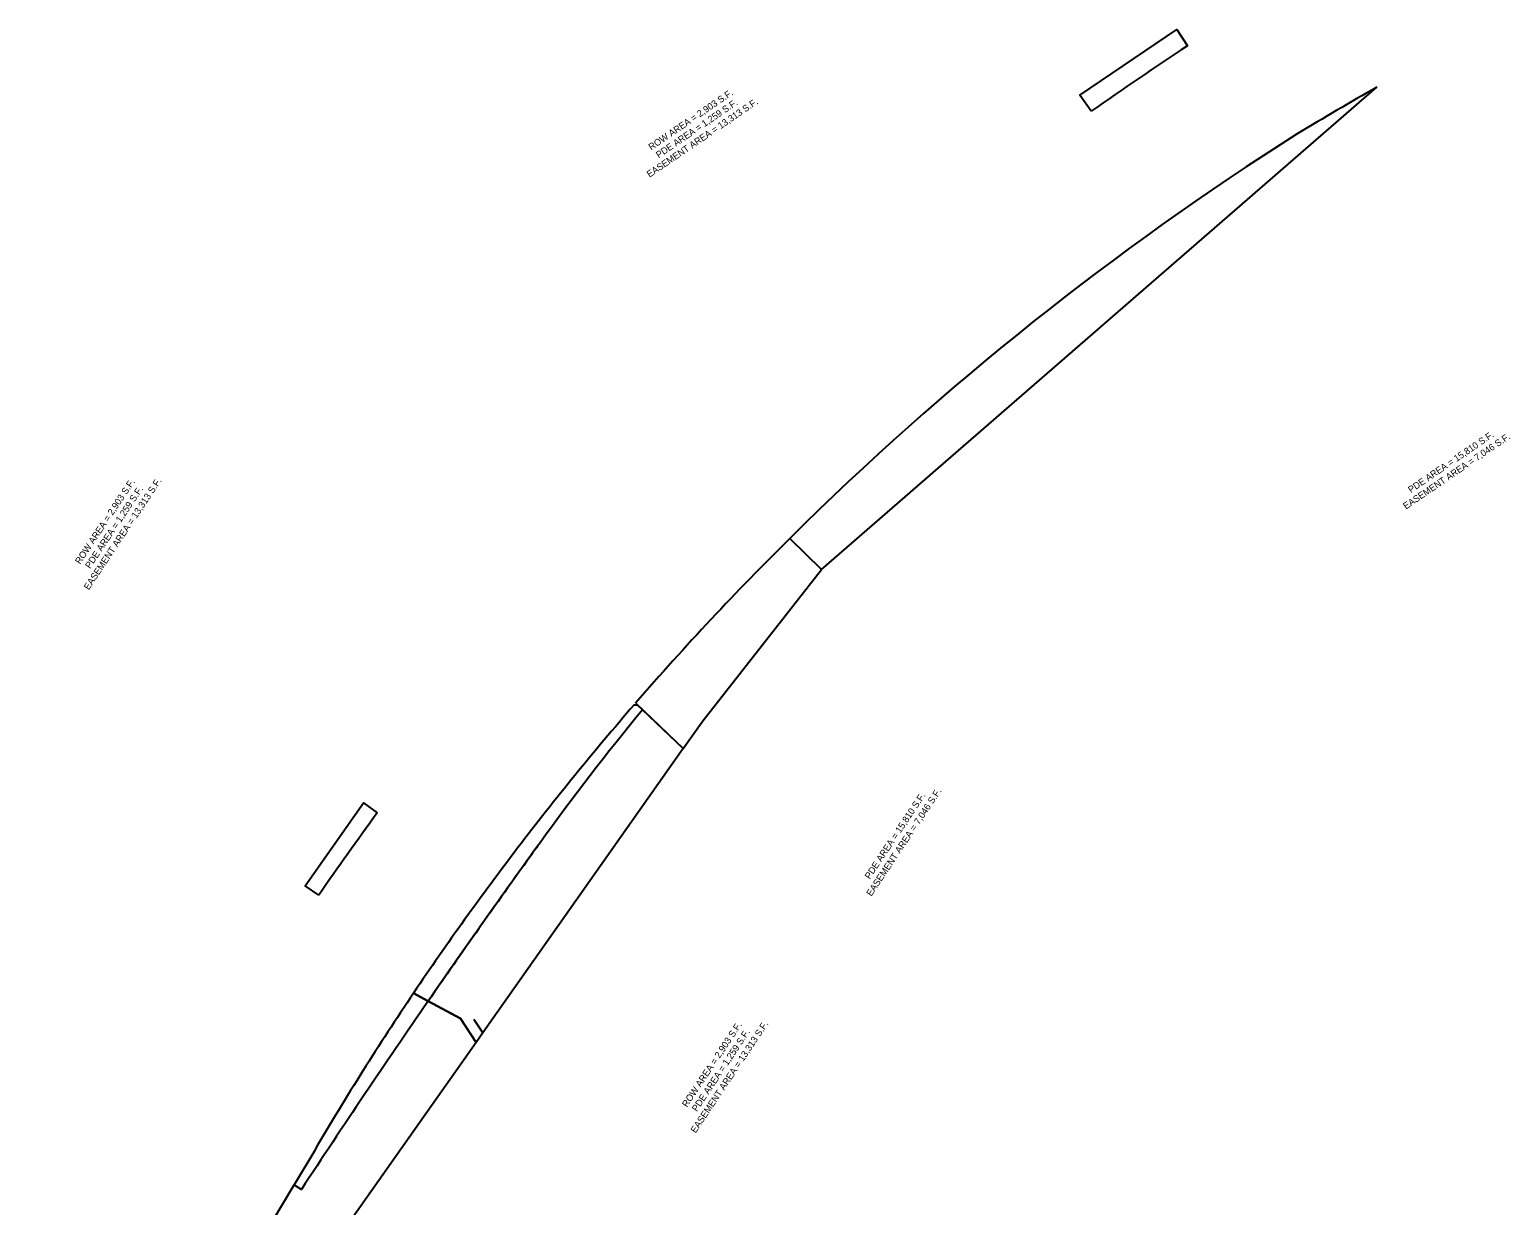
# Model space of a CAD drawing. Extents: x 2379754 to 2381218, y 331426 to 332977.
# Drawn here: x 2380108 to 2381218, y 332096 to 332977 of the extents above; entities that cross this region are included whole.
import ezdxf

# ---------------------------------------------------------------- set-up
doc = ezdxf.new("R2010")
doc.units = 0
for name, color, linetype in [('CTL Secondary Horizontal and Vertical CELL', 7, 'Continuous'), ('Exist Structure Major Bridge Seat Cogo Point CELL', 7, 'Continuous'), ('Pattern_29', 7, 'Continuous')]:
    doc.layers.add(name, color=color, linetype=linetype)

msp = doc.modelspace()

# ---------------------------------------------------------------- linework, layer by layer
at = {"layer": 'CTL Secondary Horizontal and Vertical CELL'}
for points in [[(2380903.7, 332915.8), (2380895.2, 332927.9), (2380967.8, 332977), (2380975.7, 332964.8)], [(2380677.7, 332595.7), (2380701.6, 332572.5), (2381117.6, 332933.9)]]:
    msp.add_lwpolyline(points, dxfattribs=at)
for centre, radius, start, end in [((2382262.2, 330998.3), 2350, 123.1929, 125.3158), ((2382633, 330287), 3050, 119.7915, 121.0889), ((2382262.2, 330998.3), 2250, 122.3553, 134.7668)]:
    msp.add_arc(centre, radius, start, end, dxfattribs=at)
at = {"layer": 'Exist Structure Major Bridge Seat Cogo Point CELL'}
for points in [[(2380562.3, 332472.3), (2380598, 332438.4), (2380612.6, 332459.1), (2380701.6, 332572.5), (2380677.7, 332595.7)], [(2380567.5, 332467.4), (2380598, 332438.4), (2380447.7, 332225.2), (2380441.4, 332234.9), (2380447.7, 332225.2), (2380442.8, 332218.1), (2380431.1, 332235.9), (2380406.9, 332249)], [(2380324.9, 332328.4), (2380314.7, 332335.5), (2380358.3, 332397.5), (2380368.7, 332390.1)], [(2380406.9, 332249), (2380431.1, 332235.9), (2380442.8, 332218.1), (2380274.2, 331978.9), (2380108.2, 331778.2)], [(2380116.1, 331792.1), (2380306.4, 332111.4), (2380311.8, 332107.8)]]:
    msp.add_lwpolyline(points, dxfattribs=at)
for centre, radius, start, end in [((2382262.2, 330998.3), 2250, 134.7668, 139.071), ((2382124.6, 331188.5), 2015, 140.6049, 144.1843), ((2382262.2, 330998.3), 2350, 143.6824, 145.5272), ((2386191.3, 328253.9), 7030, 144.18428, 145.36833), ((2386191.3, 328253.9), 7030, 145.36833, 146.75558)]:
    msp.add_arc(centre, radius, start, end, dxfattribs=at)
at = {"layer": 'Pattern_29'}
for p, q in [((2380406.9, 332249), (2380395.9, 332254.9)), ((2380395.9, 332254.9), (2380406.9, 332249))]:
    msp.add_line(p, q, dxfattribs=at)
for points in [[(2380567.5, 332467.4), (2380567.4, 332467.4), (2380563.7, 332470.9), (2380561.1, 332470.9)], [(2380321.8, 332137.3), (2380321.8, 332137.1), (2380306.4, 332111.4), (2380311.8, 332107.8)]]:
    msp.add_lwpolyline(points, dxfattribs=at)
for centre, radius, start, end in [((2382262.2, 330998.3), 2250, 139.1167, 142.6278), ((2382124.6, 331188.5), 2015, 140.6049, 144.1843), ((2386191.3, 328253.9), 7030, 144.18428, 144.28733), ((2382262.2, 330998.3), 2250, 142.6278, 146.0467), ((2386191.3, 328253.9), 7030, 144.28733, 145.36833), ((2382262.2, 330998.3), 2250, 146.0486, 149.5863), ((2382262.2, 330998.3), 2250, 146.0467, 146.0486), ((2386191.3, 328253.9), 7030, 145.36833, 146.75558)]:
    msp.add_arc(centre, radius, start, end, dxfattribs=at)

# ---------------------------------------------------------------- texts
at = {"layer": 'CTL Secondary Horizontal and Vertical CELL'}
for s, rotation, p in [('PDE AREA = 1,259 S.F.', 34.2806, (2380579.6, 332880.5)), ('PDE AREA = 15,810 S.F.', 34.2806, (2381143.2, 332629.6)), ('PDE AREA = 1,259 S.F.', 56.361, (2380153.5, 332572.7)), ('PDE AREA = 15,810 S.F.', 56.361, (2380737.7, 332340)), ('PDE AREA = 1,259 S.F.', 56.361, (2380608.2, 332165.8))]:
    msp.add_text(s, height=5, rotation=rotation, dxfattribs=at).set_placement(p)
at = {"layer": 'Exist Structure Major Bridge Seat Cogo Point CELL'}
for s, rotation, p in [('EASEMENT AREA = 13,313 S.F.', 34.2806, (2380572.7, 332866)), ('EASEMENT AREA = 7,046 S.F.', 34.2806, (2381139.5, 332617.3)), ('EASEMENT AREA = 13,313 S.F.', 56.361, (2380152.5, 332556.7)), ('EASEMENT AREA = 7,046 S.F.', 56.361, (2380738.9, 332327.2)), ('EASEMENT AREA = 13,313 S.F.', 56.361, (2380607.2, 332149.7))]:
    msp.add_text(s, height=5, rotation=rotation, dxfattribs=at).set_placement(p)
at = {"layer": 'Pattern_29'}
for rotation, p in [(34.2806, (2380574, 332886.4)), (56.361, (2380146, 332576)), (56.361, (2380600.8, 332169.1))]:
    msp.add_text('ROW AREA = 2,903 S.F.', height=5, rotation=rotation, dxfattribs=at).set_placement(p)

doc.saveas('drawing.dxf')
